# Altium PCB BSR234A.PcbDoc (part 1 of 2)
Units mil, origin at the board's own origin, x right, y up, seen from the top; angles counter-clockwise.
Board outline 3000 x 2500 mil, 4 copper layers (Top Layer, Signal Layer 1, Signal Layer 2, Bottom Layer), stack 61.2 mil thick; 82 components, 24 nets, 148 pads, 419 vias.
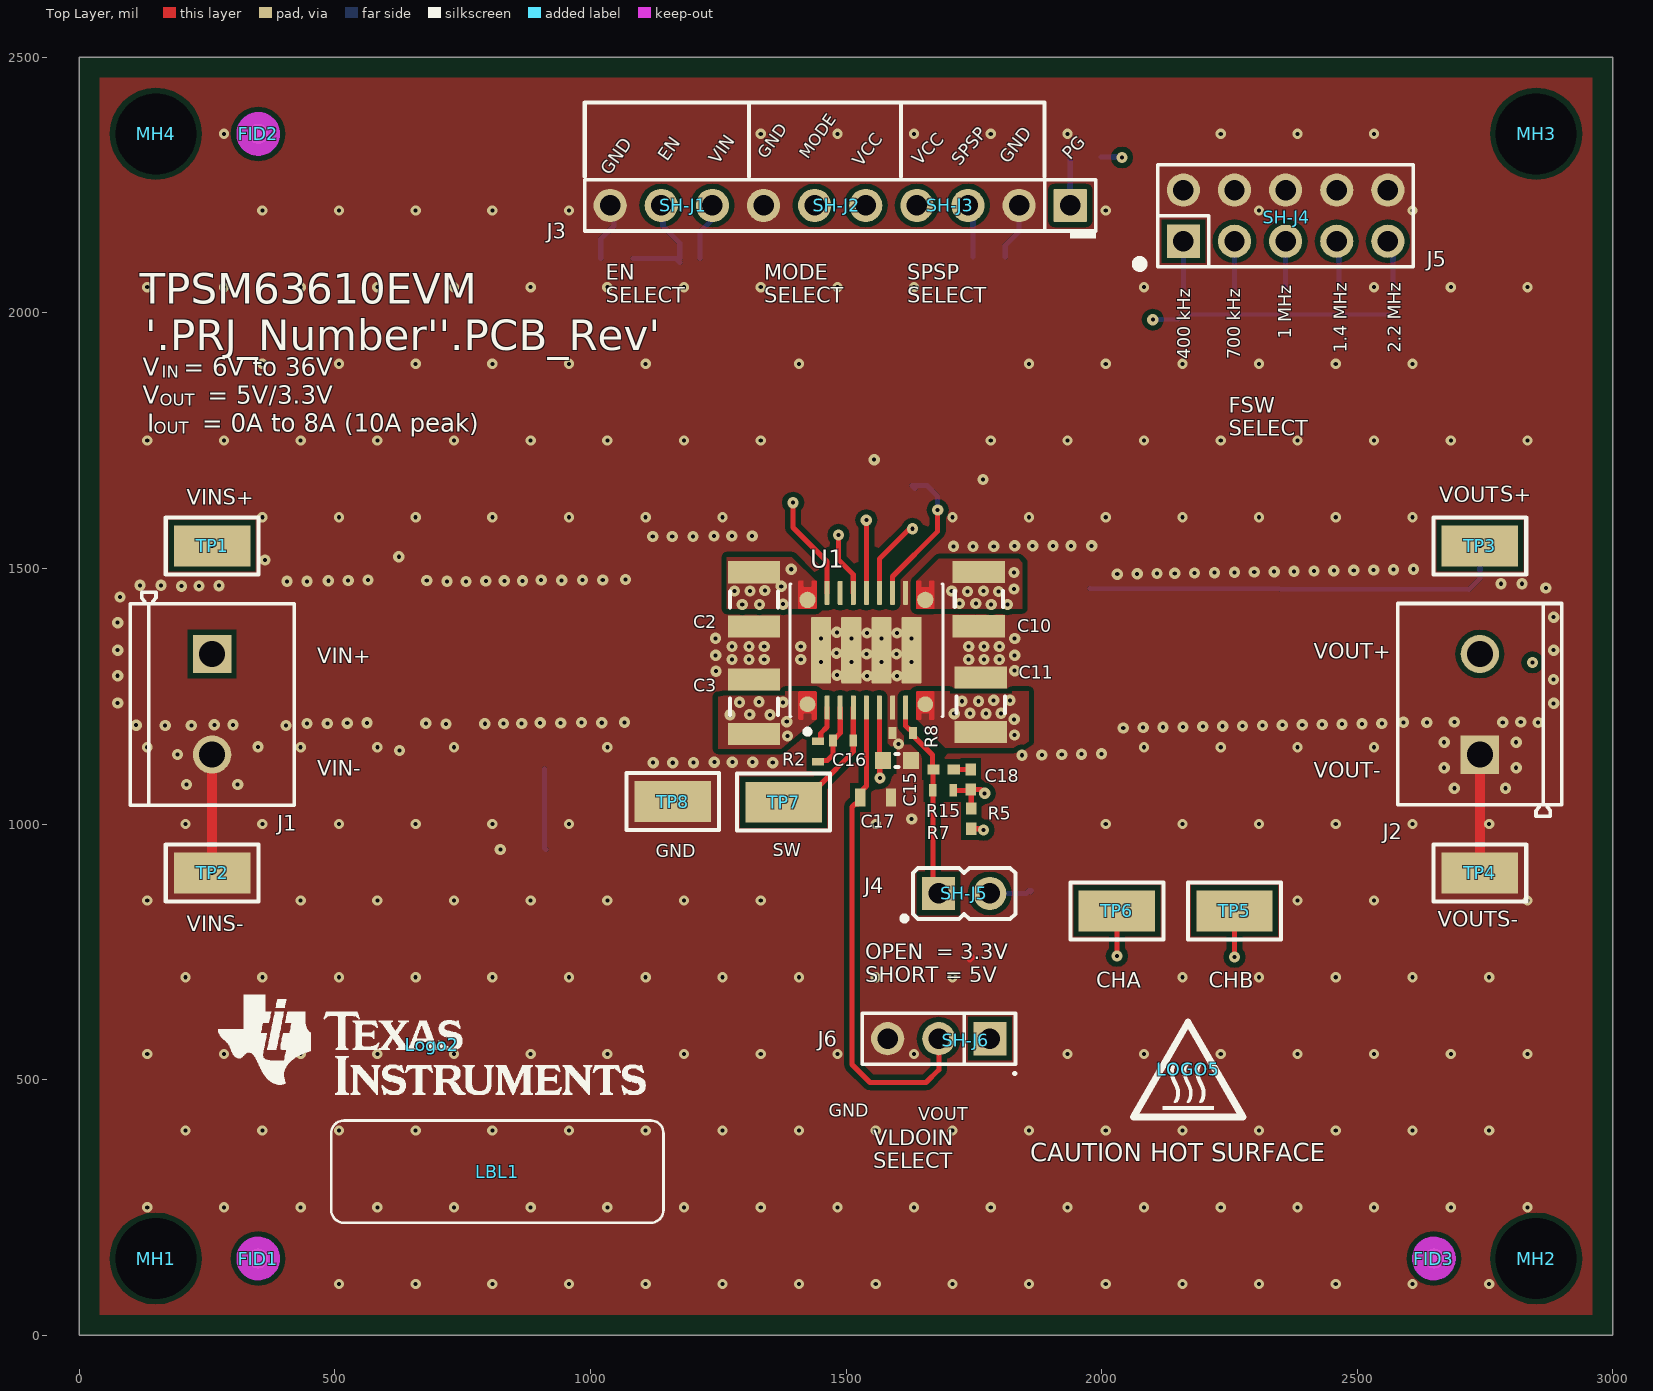
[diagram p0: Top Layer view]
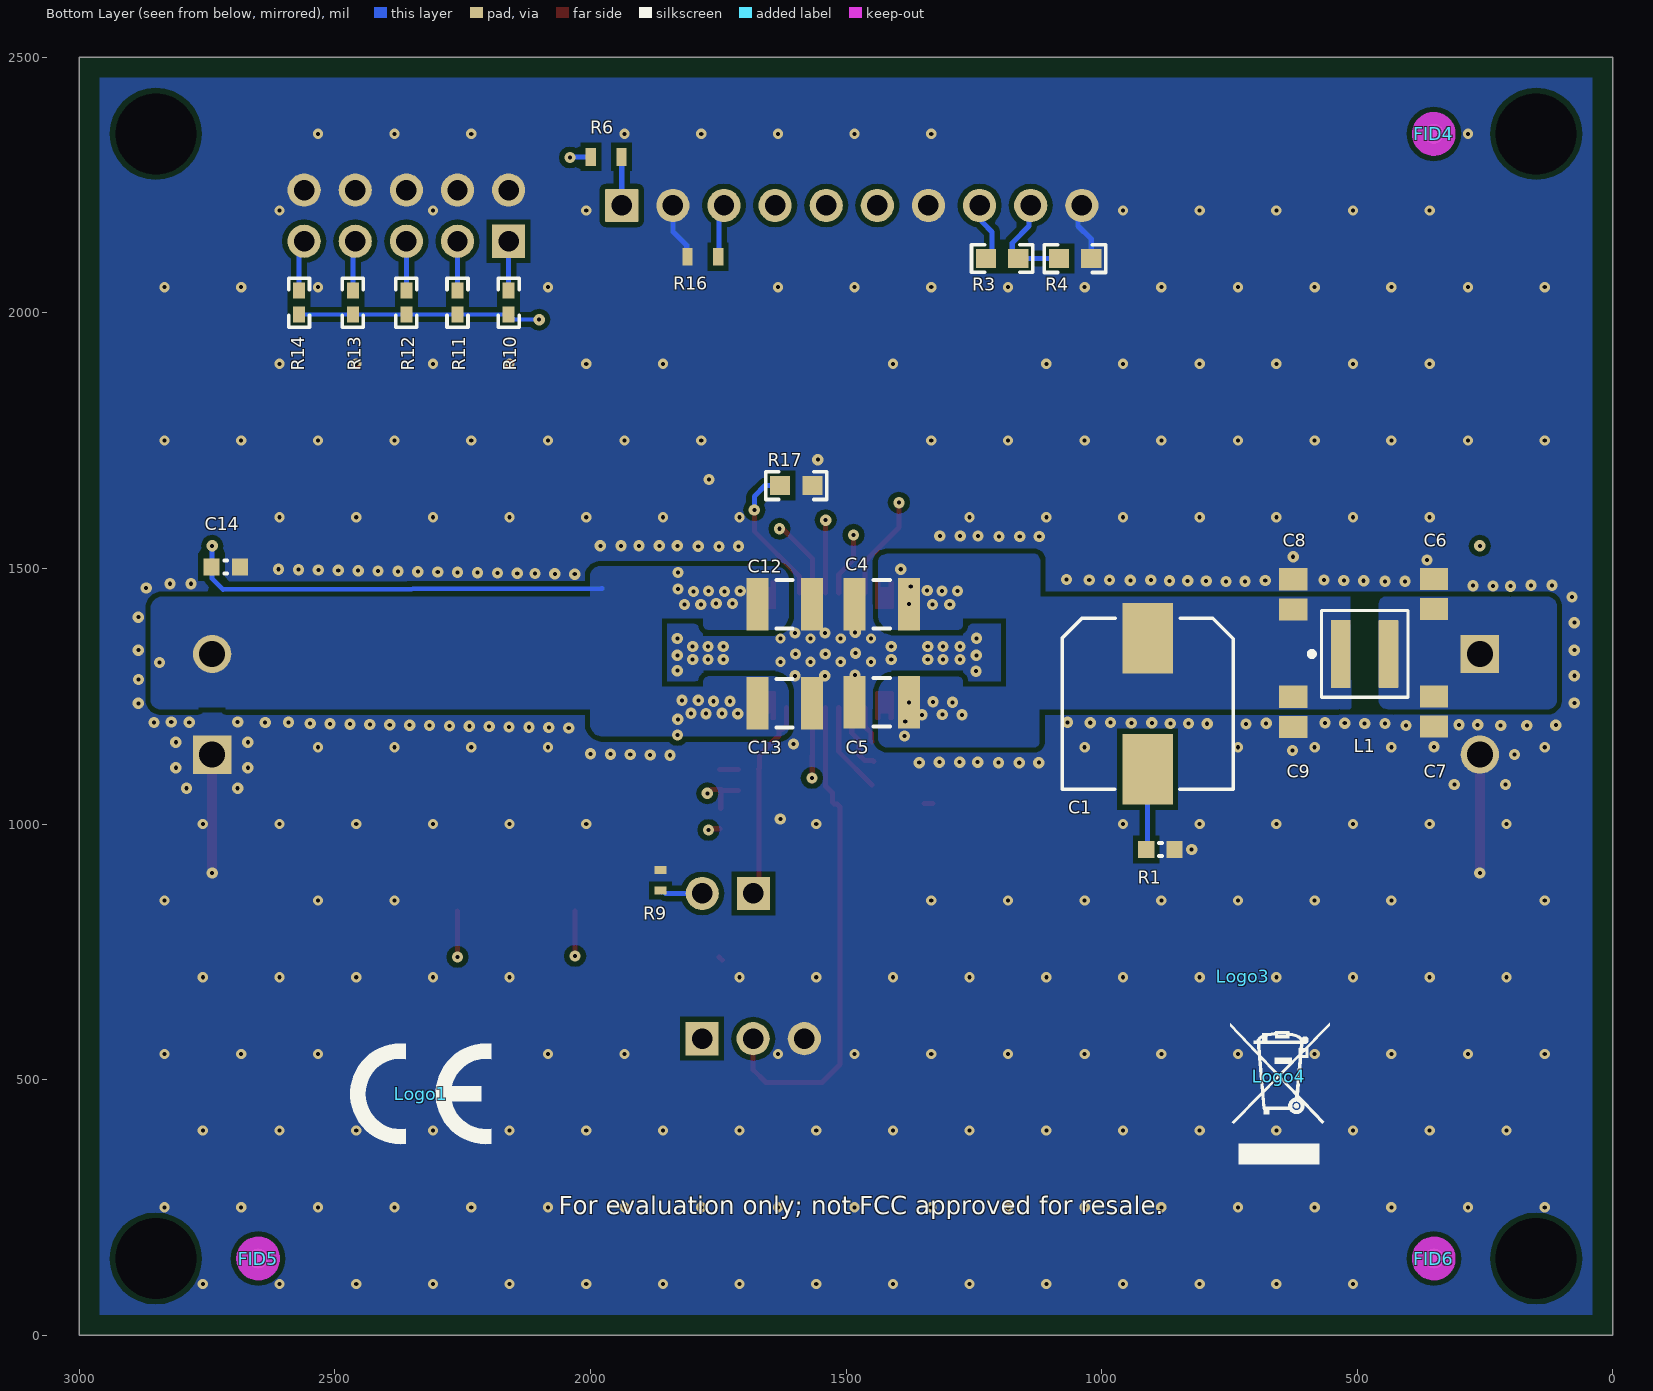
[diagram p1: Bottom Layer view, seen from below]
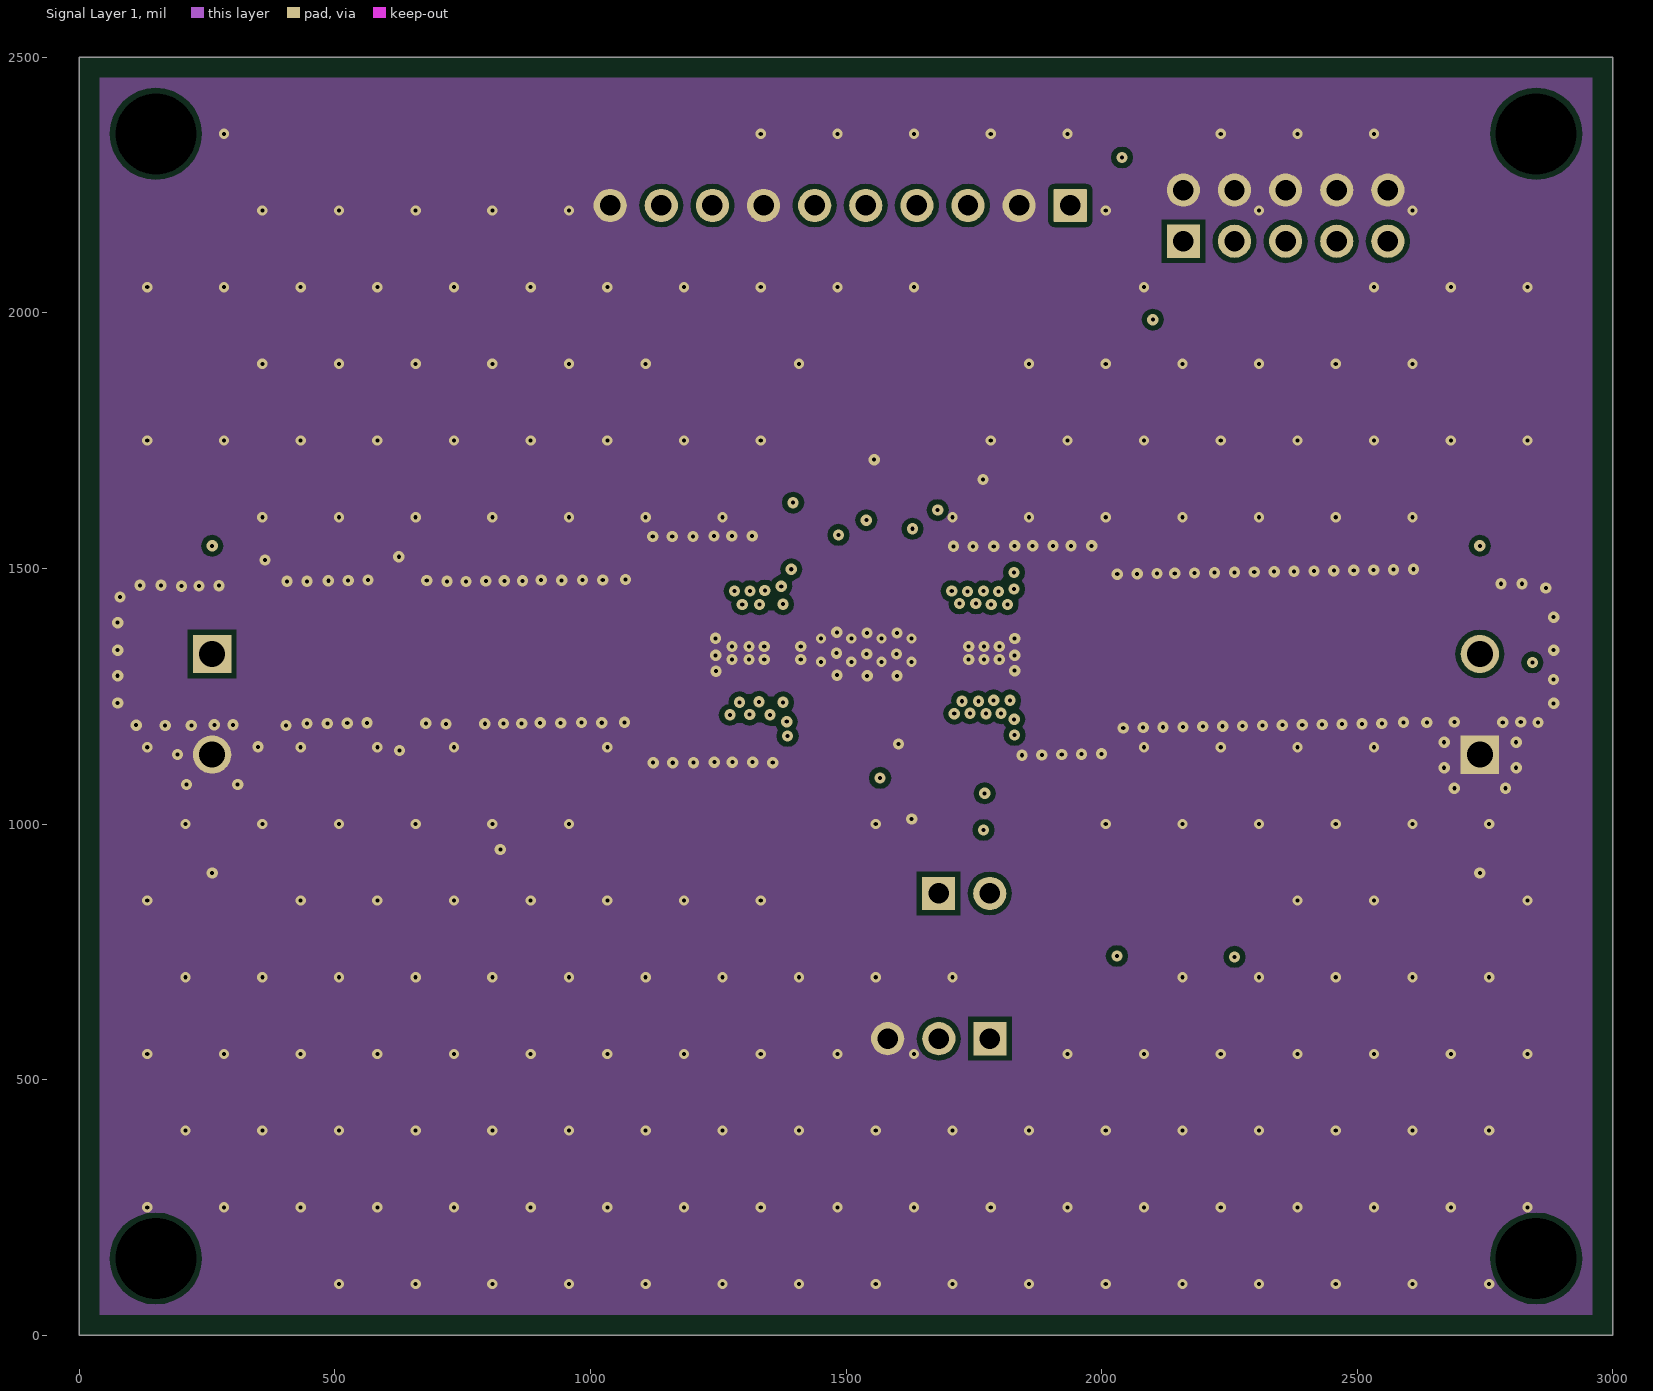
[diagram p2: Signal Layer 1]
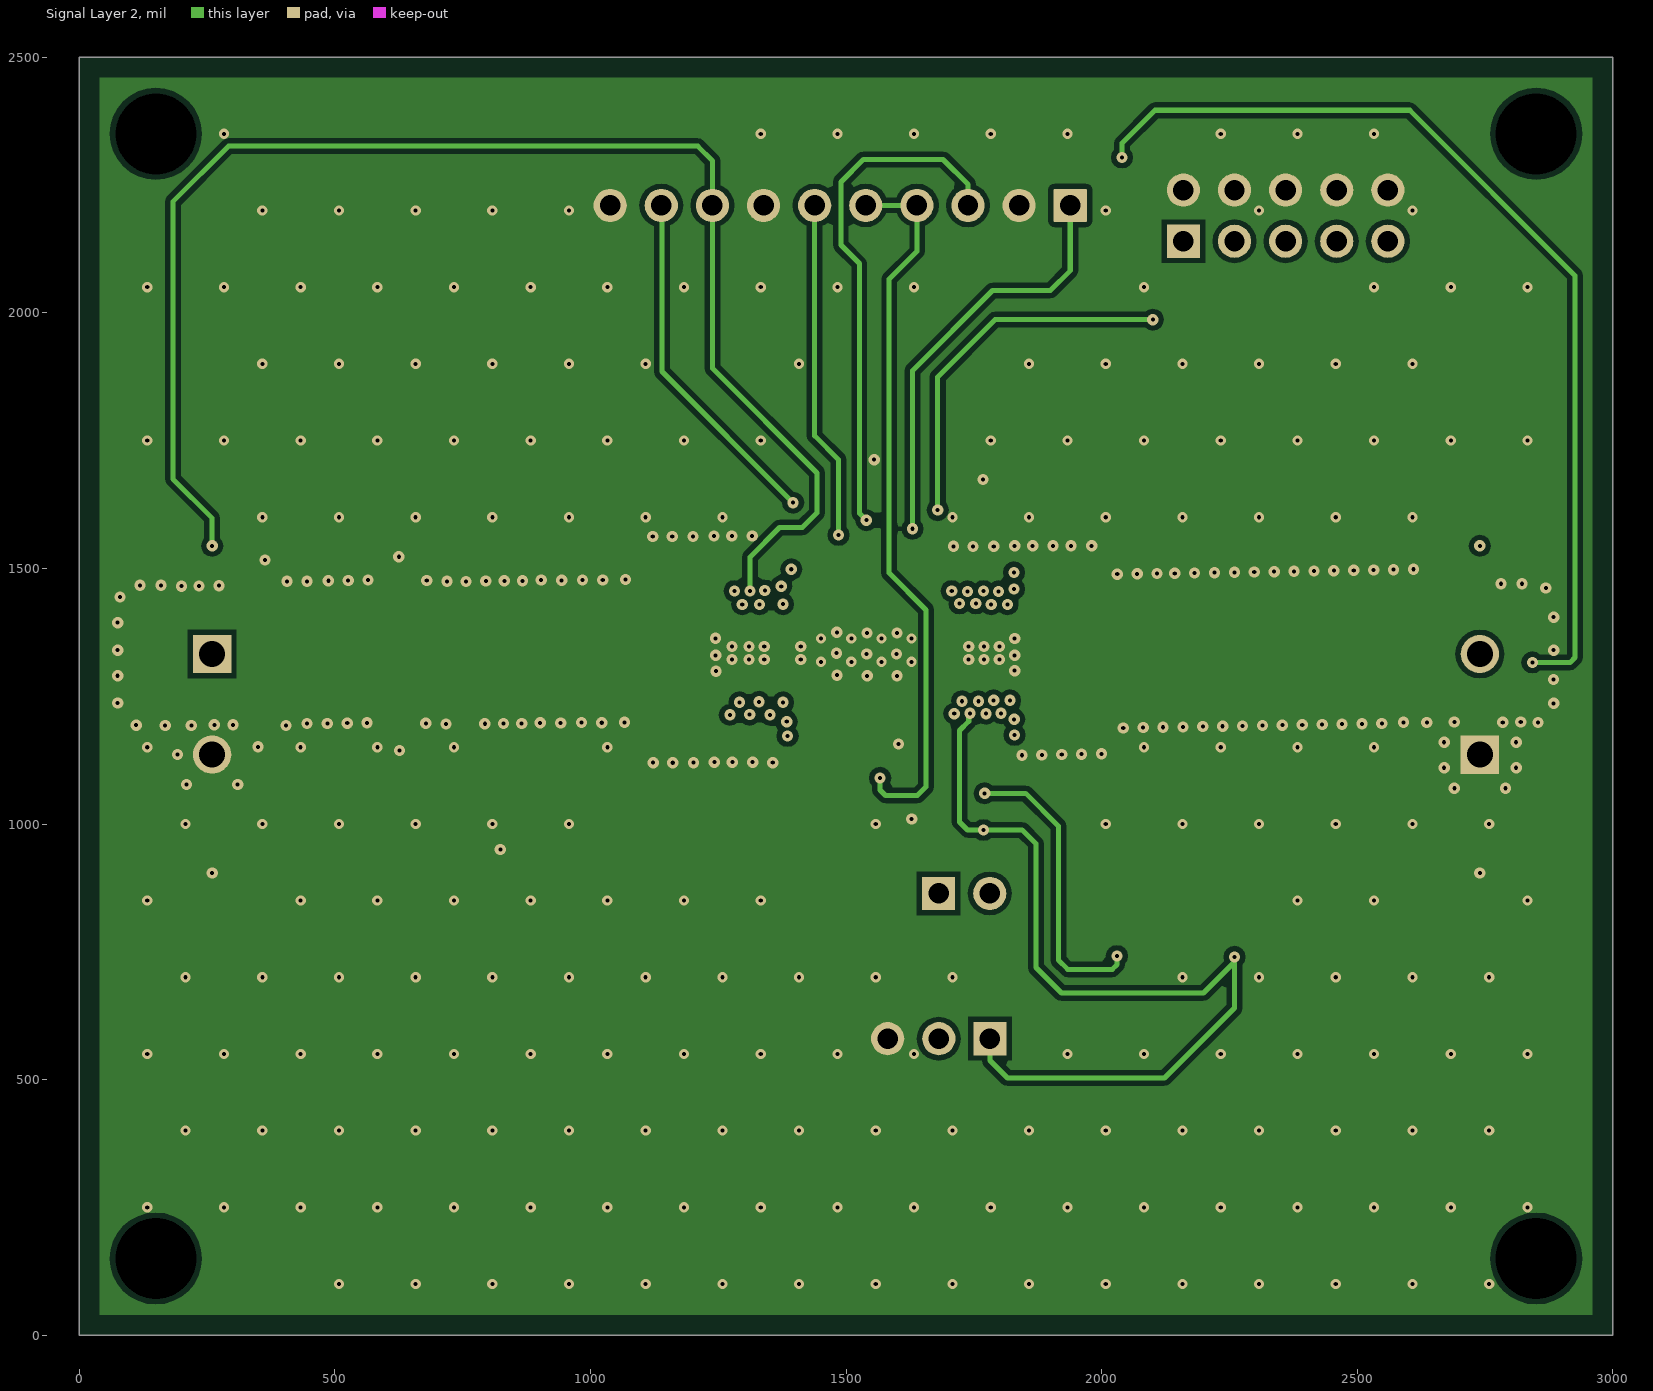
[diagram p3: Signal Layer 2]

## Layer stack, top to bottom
Top Solder: solder mask 0.4, Solder Resist, Dk 3.5
Top Layer: signal copper 2.8
Dielectric1: core 5, FR-4 High Tg, Dk 4.8
Signal Layer 1: signal copper 2.8
Dielectric3: dielectric 40, FR-4 High Tg, Dk 4.8
Signal Layer 2: signal copper 2.8
Dielectric2: dielectric 5, FR-4 High Tg, Dk 4.8
Bottom Layer: signal copper 2.8
Bottom Solder: solder mask 0.4, Solder Resist, Dk 3.5

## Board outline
0,0 3000,0 3000,2500 0,2500

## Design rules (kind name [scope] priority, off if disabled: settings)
AcuteAngle [All] p1: minimum=4.50000000000000E+0001 checktracksonly=FALSE
AssemblyTestPointUsage [All] p1: valid=2
BoardOutlineClearance BoardOutlineClearance_MountingHoles [OnCopper and InComponentClass('Mounting Holes')] p1: gap=39.37 ignorepadtopadclearanceinfootprint=FALSE
BoardOutlineClearance BoardOutlineClearance_Poly [OnCopper and IsPoly] p2: gap=40 ignorepadtopadclearanceinfootprint=FALSE
BoardOutlineClearance [OnCopper and Not InComponentClass('Logo') and not InComponentClass('FiducialMark') and not InRegion(1000,500,4000,800) and not InPoly] p3: gap=50 ignorepadtopadclearanceinfootprint=FALSE
Clearance Clearance_Keepouts [((IsTrack Or IsArc) And Not InPoly) And IsFree and IsKeepOut vs ((IsTrack Or IsArc) And Not InPoly) And IsFree and IsKeepOut] p1: gap=0 ignorepadtopadclearanceinfootprint=FALSE
Clearance Clearance_Poly [InPolygon] p2: gap=10 ignorepadtopadclearanceinfootprint=TRUE
Clearance Clearance_FiducialMark [IsKeepOut and InComponentClass('FiducialMark') vs IsPad and InComponentClass('FiducialMark')] p3: gap=0 ignorepadtopadclearanceinfootprint=FALSE
Clearance [All] p4: gap=7.87 ignorepadtopadclearanceinfootprint=TRUE
ComponentClearance ComponentClearance_MountingHoles_FiducialMarks [InComponentClass('Mounting Holes') vs InComponentClass('FiducialMark')] p1: gap=50 collisioncheckmode=3 verticalgap=10 showdistances=FALSE
ComponentClearance ComponentClearance_Shunt [InComponentClass('Header') vs InComponentClass('Shunt')] p2: gap=0 collisioncheckmode=3 verticalgap=0 showdistances=FALSE
ComponentClearance ComponentClearance_Logo [InComponentClass('Logo')] p3: gap=50 collisioncheckmode=3 verticalgap=10 showdistances=FALSE
ComponentClearance ComponentClearance_ScrewToNut [(HasFootprint('NY PMS 440 0025 PH')) vs (HasFootprint('Keystone_1902C'))] p4: gap=5 collisioncheckmode=3 verticalgap=10 showdistances=FALSE
ComponentClearance ComponentClearance_MountingHoles [InComponentClass('Mounting Holes')] p5: gap=250 collisioncheckmode=3 verticalgap=100000 showdistances=FALSE
ComponentClearance ComponentClearance_SmallPassives [HasFootprint('0201*') or HasFootprint('0402*') or HasFootprint('0508') or HasFootprint('0603*') or HasFootprint('0612') or HasFootprint('0805*') or HasFootprint('0815*') or HasFootprint('0830*') or HasFootprint('1206*') or HasFootprint('1210*') or HasFootprint('1808*') or HasFootprint('1812*') or HasFootprint('1825*') or HasFootprint('2010*') or HasFootprint('2220*') or HasFootprint('2225*') or HasFootprint('2512*') or HasFootprint('2728*') or HasFootprint('3518*') vs HasFootprint('0201*') or HasFootprint('0402*') or HasFootprint('0508') or HasFootprint('0603*') or HasFootprint('0612') or HasFootprint('0805*') or HasFootprint('0815*') or HasFootprint('0830*') or HasFootprint('1206*') or HasFootprint('1210*') or HasFootprint('1808*') or HasFootprint('1812*') or HasFootprint('1825*') or HasFootprint('2010*') or HasFootprint('2220*') or HasFootprint('2225*') or HasFootprint('2512*') or HasFootprint('2728*') or HasFootprint('3518*')] p6: gap=14.96 collisioncheckmode=3 verticalgap=10 showdistances=FALSE
ComponentClearance ComponentClearance_THtoSMT [IsThruComponent vs IsSMTComponent] p7: gap=40 collisioncheckmode=3 verticalgap=30 showdistances=FALSE
ComponentClearance ComponentClearance_THtoTH [IsThruComponent vs IsThruComponent] p8: gap=30 collisioncheckmode=3 verticalgap=30 showdistances=FALSE
ComponentClearance ComponentClearance_NetTie [HasFootprint('Net-Tie_10milWide_30milLong')] p9: gap=0 collisioncheckmode=3 verticalgap=0 showdistances=FALSE
ComponentClearance [All] p10: gap=15 collisioncheckmode=3 verticalgap=10 showdistances=FALSE
DiffPairsRouting [All] p1: maxlimit=100 minlimit=10 mostfreqgap=10 toplayer_minwidth=15 toplayer_maxwidth=15 toplayer_prefwidth=15 midlayer1_minwidth=15 midlayer1_maxwidth=15 midlayer1_prefwidth=15 midlayer2_minwidth=15 midlayer2_maxwidth=15 midlayer2_prefwidth=15 bottomlayer_minwidth=15 bottomlayer_maxwidth=15 bottomlayer_prefwidth=15 maxuncoupledlength=1000
FabricationTestPointUsage TestPointUsage [All] p1: valid=2 allowmultiple=FALSE
FabricationTestpoint Testpoint [All] p1: side=3 testpointundercomponent=TRUE minsize=40 maxsize=100 preferedsize=60 minholesize=0 maxholesize=40 preferedholesize=32 testpointgrid=1 allowsidetop=TRUE allowsidebottom=TRUE usegrid=TRUE gridtolerance=0.01
FanoutControl Fanout_LCC [IsLCC] p1: bgadir=Out bgaviamode=Centered fanoutstyle=Auto fanoutdirection=Alternating viagrid=1 // Fanout_LCC (Default Rule)
FanoutControl Fanout_BGA [IsBGA] p2: bgadir=Out bgaviamode=Centered fanoutstyle=Auto fanoutdirection=Alternating viagrid=1 // Fanout_BGA (Default Rule)
FanoutControl Fanout_Default [All] p4: bgadir=Out bgaviamode=Centered fanoutstyle=Auto fanoutdirection=Alternating viagrid=1 // Fanout_Default (Default Rule)
FanoutControl Fanout_Small [(CompPinCount < 5)] p5: bgadir=Out bgaviamode=Centered fanoutstyle=Auto fanoutdirection=OutThenIn viagrid=1 // Fanout_Small (Default Rule)
HoleSize [All] p1: absolutevalues=TRUE maxlimit=251 minlimit=7.87 maxpercent=80.000 minpercent=20.000
MinimumAnnularRing MinimumAnnularRing_ThermalPadVias [IsVia and InAnyComponent] p1: minimumring=5.91
MinimumAnnularRing [All] p2: minimumring=5.9
MinimumSolderMaskSliver MinimumSolderMaskSliver_Logo [InComponentClass('Logo') vs InComponentClass('Logo')] p1: minsoldermaskwidth=0.7
MinimumSolderMaskSliver [All] p2: minsoldermaskwidth=3.94
PlaneConnect [All] p1: planeconnectstyle=Relief reliefexpansion=10 reliefentries=4 reliefconductorwidth=10 reliefairgap=10
PolygonConnect PolygonConnect_TH [IsThruPin] p1: connectstyle=Direct reliefconductorwidth=10 reliefentries=4 polygonreliefangle="90 Angle" airgapwidth=10
PolygonConnect [All] p2: connectstyle=Direct reliefconductorwidth=10 reliefentries=4 polygonreliefangle="90 Angle" airgapwidth=10
RoutingVias ThermalPadVias [IsVia and InAnyComponent] p1: holewidth=7.87 width=19.68 viastyle="Through Hole" minholewidth=7.87 minwidth=19.68 maxholewidth=12.99 maxwidth=23.62
RoutingVias [All] p2: holewidth=10 width=22 viastyle="Through Hole" minholewidth=7.87 minwidth=8 maxholewidth=40 maxwidth=65
SilkToBoardRegionClearance [Not ((IsComment or IsDesignator) And (Hide <> 'False')) and not InRegion(1000,500,4000,800)] p1:
SilkToSilkClearance SilkToSilkClearance_Pb-FreeLogo [(HasFootprint('Pb-Free_Overlay_Medium') OR HasFootprint('Pb-Free_Overlay_Small')) vs (HasFootprint('Pb-Free_Overlay_Medium') OR HasFootprint('Pb-Free_Overlay_Small'))] p1: silktosilkclearance=0
SilkToSilkClearance [All] p2: silktosilkclearance=3.94
SilkToSolderMaskClearance SilkToComponentPadClearance [(IsPad or IsFill or IsRegion) and InAnycomponent] p1: minsilkscreentomaskgap=5 clearancetoexposedcopper=TRUE
SilkToSolderMaskClearance "Silk to Solder Mask Opening" [All] p2: minsilkscreentomaskgap=3.94 clearancetoexposedcopper=FALSE
SolderMaskExpansion [All] p1: expansion=1.97 istentingtop=FALSE
UnRoutedNet [All] p1: checkbadconnections=TRUE
Width [All] p1: maxlimit=100 minlimit=6 preferedwidth=10 checkconnectedcopper=TRUE
14 further rules are at their usual default settings.

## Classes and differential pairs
component class AssemblyNote: ZZ1 ZZ2 ZZ3 ZZ4 ZZ5 ZZ6 ZZ7 ZZ8 ZZ9
component class FiducialMark: FID1 FID2 FID3 FID4 FID5 FID6
component class Logo: Logo2
component class BSR234A_Hardware: !PCB1 FID1 FID2 FID3 FID4 FID5 FID6 H1 H2 H3 H4 H5 H6 H7 H8 LBL1 Logo1 Logo2 Logo3 Logo4 LOGO5 MH1 MH2 MH3 MH4 SH-J1 SH-J2 SH-J3 SH-J4 SH-J5 SH-J6 ZZ1 ZZ2 ZZ3 ZZ4 ZZ5 ZZ6 ZZ7 ZZ8 ZZ9
component class BSR234A: C1 C2 C3 C4 C5 C6 C7 C8 C9 C10 C11 C12 C13 C14 C15 C16 C17 C18 J1 J2 J3 J4 J5 J6 L1 R1 R2 R3 R4 R5 R6 R7 R8 R9 R10 R11 R12 R13 R14 R15 R16 R17 TP1 TP2 TP3 TP4 TP5 TP6 TP7 TP8 U1
component class Header: J3 J4 J5 J6
component class Shunt: SH-J1 SH-J2 SH-J3 SH-J4 SH-J5 SH-J6
component class Label: LBL1

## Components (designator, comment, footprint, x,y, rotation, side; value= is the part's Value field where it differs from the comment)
C1 "UUD1H101MNL1GS" SM_RADIAL_8MM 910,1235 r270 bottom value=100uF
C2 "GRM32ER71H106KA12L" 1210_270L 1320.16,1439.32 r90 top value=10uF
C3 "GRM32ER71H106KA12L" 1210_270L 1320.16,1229.32 r270 top value=10uF
C4 "GRM32ER71H106KA12L" 1210_270L 1430,1430 r180 bottom value=10uF
C5 "GRM32ER71H106KA12L" 1210_270L 1430,1238 r180 bottom value=10uF
C6 "CGA4J3X7R1H225K125AB" 0805L 350,1450 r90 bottom value=2.2uF
C7 "CGA4J3X7R1H225K125AB" 0805L 350,1220 r270 bottom value=2.2uF
C8 "CGA4J3X7R1H225K125AB" 0805L 625.16,1449.32 r90 bottom value=2.2uF
C9 "CGA4J3X7R1H225K125AB" 0805L 625.16,1219.32 r270 bottom value=2.2uF
C10 "GRM32EC81C476ME15L" 1210_270L 1760,1440 r90 top value=47uF
C11 "GRM32EC81C476ME15L" 1210_270L 1763.8,1233.35 r270 top value=47uF
C12 "GRM32EC81C476ME15L" 1210_270L 1620,1430 r180 bottom value=47uF
C13 "GRM32EC81C476ME15L" 1210_270L 1620,1236.11 r180 bottom value=47uF
C14 "CGA3E2X7R1E104K080AA" 0603L 2713.43,1502.69 r180 bottom value=0.1uF
C15 "Capacitor" 0603L 1599.89,1124.58 r0 top value=1uF
C16 "CBOOT" 0402S 1494.41,1163.53 r180 top value=0.1uF
C17 "CBIAS" 0603S 1557.93,1051.76 r180 top value=0.15uF
C18 "CGA2B2C0G1H100D050BA" 0402L 1744.06,1087.07 r90 top value=10pF
FID1 "Fiducial" Fiducial10-20 350,150 r0 top
FID2 "Fiducial" Fiducial10-20 350,2350 r0 top
FID3 "Fiducial" Fiducial10-20 2650,150 r0 top
FID4 "Fiducial" Fiducial10-20 350,2350 r180 bottom
FID5 "Fiducial" Fiducial10-20 2650,150 r180 bottom
FID6 "Fiducial" Fiducial10-20 350,150 r180 bottom
J1 "1729018" Phoenix_1729018 260,1234.16 r270 top
J2 "1729018" Phoenix_1729018 2740,1234.16 r90 top
J3 "TSW-110-07-G-S" TSW-110-07-G-S 1488.67,2210 r180 top
J4 "PBC02SAAN" Sullins_PBC02SAAN 1731.23,864.16 r90 top
J5 "PEC05DAAN" CONN_PEC05DAAN 2360,2190 r0 top
J6 "PBC03SAAN" PBC03SAAN 1681.57,580 r180 top
L1 "XGL4030-152MEC" FP-XGL4030-152MEC_SMT2_4MM0_4MM0-MFG 485.35,1332.58 r180 bottom value=1.5uH
LBL1 "THT-14-423-10" Label_650x200 817.95,320 r180 top
Logo1 "CE Mark" CE_Mark_5mm 2332,472 r180 bottom
Logo2 "Texas Instruments" TI_Stacked_Overlay_Small 690,568.18 r0 top
Logo3 "FCC disclaimer" FCC_disclaimer 724.17,701.97 r180 bottom
Logo4 "WEEE logo" WEEE_Minimum 653,507 r180 bottom
LOGO5 "CAUTION HOT SURFACE" IEC_HotSurface_Small 2169.25,520 r0 top
MH1 "MTG_NoPads" MTG_159mil 150,150 r0 top
MH2 "MTG_NoPads" MTG_159mil 2850,150 r0 top
MH3 "MTG_NoPads" MTG_159mil 2850,2350 r0 top
MH4 "MTG_NoPads" MTG_159mil 150,2350 r0 top
R1 "CRCW06030000Z0EA" 0603L 885,950 r0 bottom value=0
R2 "CRCW04020000Z0EDHP" 0402S 1445.09,1142.06 r270 top value=0
R3 "CRCW0603187KFKEA" 0603 1194.45,2106.16 r180 bottom value=187k
R4 "CRCW060349K9FKEA" 0603 1051.83,2106.16 r0 bottom value=49.9k
R5 "CRCW040210R0FKED" 0402L 1745.01,1010.46 r270 top value=10.0
R6 "RRESET" 0603S 1969.2,2304.98 r0 bottom value=100k
R7 "RFBT" 0402S 1690,1065.91 r0 top value=100k
R8 "RFBB" 0402S 1611.03,1177.8 r0 top value=43.2k
R9 "RFBB5V" 0402S 1863.08,890 r270 bottom value=59.0k
R10 "CRCW040240K2FKED" 0402 2160,2020 r270 bottom value=40.2k
R11 "CRCW040222K6FKED" 0402 2260,2020 r270 bottom value=22.6k
R12 "CRCW040215K8FKED" 0402 2360,2020 r270 bottom value=15.8k
R13 "CRCW040211K0FKED" 0402 2464.6,2020 r270 bottom value=11.0k
R14 "CRCW04026K80JNED" 0402 2570,2020 r270 bottom value=6.8k
R15 "CRCW04024K99FKED" 0402L 1691.07,1106.38 r0 top value=4.99k
R16 "CRCW060316K5FKEA" 0603S 1780,2109.7 r180 bottom value=16.5k
R17 "CRCW06034M99FKEA" 0603 1597.25,1662 r0 bottom value=4.99Meg
SH-J1 "SNT-100-BK-G" SNT-100-BK-G 1181.52,2210 r180 top value=1x2
SH-J2 "SNT-100-BK-G" SNT-100-BK-G 1481.52,2210 r180 top value=1x2
SH-J3 "SNT-100-BK-G" SNT-100-BK-G 1704.05,2210 r0 top value=1x2
SH-J4 "SNT-100-BK-G" SNT-100-BK-G 2362,2187 r270 top value=1x2
SH-J5 "SNT-100-BK-G" SNT-100-BK-G 1731.23,864.16 r0 top value=1x2
SH-J6 "SNT-100-BK-G" SNT-100-BK-G 1734.74,577.22 r180 top value=1x2
TP1 "VIN+" Keystone_5019 260,1544.16 r0 top
TP2 "VIN-" Keystone_5019 260,904.16 r180 top
TP3 "5019" Keystone_5019 2740,1544.16 r180 top
TP4 "5019" Keystone_5019 2740,904.16 r180 top
TP5 "CHB" Keystone_5019 2260,830 r180 top
TP6 "CHA" Keystone_5019 2030,830 r0 top
TP7 "SW" Keystone_5019 1377.82,1042.64 r0 top
TP8 "GND" Keystone_5019 1161.01,1043.91 r0 top
U1 "TPSM63610RDFR" RDF0022A-MFG 1539.85,1340 r90 top
ZZ1 "This Assembly Note is for PCB labels only" AssemblyNoteLabel 160,3920 r0 top
ZZ2 "These assemblies must be clean and free from flux and all contaminants. Use of no clean flux is not acceptable." AssemblyNote 158.91,3819.12 r0 top
ZZ3 "These assemblies must comply with workmanship standards IPC-A-610 Class 2, unless otherwise specified." AssemblyNote 158.91,3726.6 r0 top
ZZ4 "Place SH-J1 on J3 pins 8 and 9" AssemblyNote 158.91,3634.08 r0 top
ZZ5 "Place SH-J2 on J3 pins 5 and 6" AssemblyNote 158.91,3541.56 r0 top
ZZ6 "Place SH-J3 on J3 pins 3 and 4" AssemblyNote 158.91,3449.04 r0 top
ZZ7 "Place SH-J4 on J5 pins 5 and 6" AssemblyNote 160,3350 r0 top
ZZ8 "Place SH-J5 on J4 pins 2 and 3" AssemblyNote 160,3240 r0 top
ZZ9 "Place SH-J6 on J6 pins 1 and 2" AssemblyNote 160,3120 r0 top

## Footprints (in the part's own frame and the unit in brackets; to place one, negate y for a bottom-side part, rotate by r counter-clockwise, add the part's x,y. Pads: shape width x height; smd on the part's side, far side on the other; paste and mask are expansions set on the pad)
0402 [mm] "0402 from SM-752 data"
  rect 0.8x0.6 smd: 1(-0.6,0) 2(0.6,0)
  silkscreen extent -1.22,-0.52 1.22,0.52, body extent -0.55,-0.3 0.55,0.3, height 0.6
0402L [mm] "0402 from SM-752 data"
  rect 0.6x0.5 smd: 1(-0.5,0) 2(0.5,0)
  body extent -0.55,-0.3 0.55,0.3, height 0.6
0402S [mil] "Based on C0402S footprint from PADS legacy"
  rect 15x24 smd: 1(-20,0) 2(20,0)
  body extent -22,-12 22,12, height 24
0603 [mm] "0603 from SM-752 data"
  rect 1x0.95 smd: 1(-0.8,0) 2(0.8,0)
  silkscreen extent -1.52,-0.69 1.52,0.69, body extent -0.87,-0.47 0.87,0.47, height 1
0603L [mm] "0603 from SM-752 data"
  rect 0.8x0.85 smd: 1(-0.7,0) 2(0.7,0)
  silkscreen extent -0.07,-0.33 0.07,0.33, body extent -0.87,-0.47 0.87,0.47, height 1
0603S [mil]
  rect 20x35 smd: 1(-30,0) 2(30,0)
  body extent -34,-19 34,19, height 39
0805L [mm] "0805 from SM-752 data"
  rect 1.1x1.4 smd: 1(-0.75,0) 2(0.75,0)
  body extent -1.1,-0.72 1.1,0.72, height 1.45
1210_270L [mm] "1210"
  rect 1.1x2.6 smd: 1(-1.35,0) 2(1.35,0)
  silkscreen extent -0.4,-1.2 0.4,1.2, body extent -1.7,-1.35 1.7,1.35, height 2.7
AssemblyNote [mil] "Assembly Note"
AssemblyNoteLabel [mil] "Assembly Note for PCB Labels"
CE_Mark_5mm [mil] "Minimum text height for CE Mark"
  silkscreen extent -138,-98 138,98
CONN_PEC05DAAN [mm] "SULLINS"
  rect 1.65x1.65 hole 1.016 mask+0: 1(-5.08,-1.27)
  round 1.65 hole 1.016 mask+0: 2(-5.08,1.27) 3(-2.54,-1.27) 4(-2.54,1.27) 5(0,-1.27) 6(0,1.27) 7(2.54,-1.27) 8(2.54,1.27) 9(5.08,-1.27) 10(5.08,1.27)
  silkscreen extent -7.45,-2.6 6.35,2.54, body extent -6.35,-2.54 6.35,2.54, height 8.38
FCC_disclaimer [mil]
Fiducial10-20 [mm]
  round 1 smd mask+0.5: 1(0,0)
  Top Layer keep-out circle w1.178: c0,0 r0.5
FP-XGL4030-152MEC_SMT2_4MM0_4MM0-MFG [mm]
  rrect10% 0.98x3.4 smd paste+0 mask+0: 1(-1.185,0) 2(1.185,0)
  silkscreen extent -2.75,-2.15 2.15,2.15, body extent -2,-2 2,2, height 3.1
IEC_HotSurface_Small [mil]
  silkscreen extent -107,-93 107,92
Keystone_5019 [mm] "Test Point, Miniature, SMT"
  rect 3.8x2.03 smd: 1(0,0)
  silkscreen extent -2.31,-1.42 2.31,1.42, body extent -1.9,-1.02 1.9,1.02, height 2.29
Label_650x200 [mil] "Thermal Transfer Label"
  round 1 on Mech13: 0(0,0)
  silkscreen extent -325,-100 325,100, body extent -325,-100 325,100, height 1
MTG_159mil [mil] "159mil Non Plated Hole"
  round 150 hole 159 unplated: 1(0,0)
PBC03SAAN [mm] "Sullins 100mil, 1x3, 230 mil above insulator"
  rect 1.65x1.65 hole 1.016: 1(-2.54,0)
  round 1.65 hole 1.016: 2(0,0) 3(2.54,0)
  silkscreen extent -3.81,-1.27 3.81,1.27, body extent -3.81,-1.27 3.81,1.27, height 8.38
Phoenix_1729018 [mm] "Phoenix Contact"
  rect 1.905x1.905 hole 1.3: 1(-2.5,0)
  round 1.9 hole 1.3: 2(2.5,0)
  silkscreen extent -5.56,-4.08 5.01,4.07, body extent -5.56,-4.08 5.01,4.07, height 10
RDF0022A-MFG [mm]
  round 0.787 smd paste+0 mask-1000: 1(-2.688,2.925) 9(-2.688,-2.925)
  rrect40% 1.2x0.25 smd paste+0 mask-1000: 2(-2.85,1.95) 3(-2.85,1.3) 4(-2.85,0.65) 5(-2.85,0) 6(-2.85,-0.65) 7(-2.85,-1.3) 8(-2.85,-1.95) 11(2.85,-1.95) 12(2.85,-1.3) 13(2.85,-0.65) 14(2.85,0) 15(2.85,0.65) 16(2.85,1.3) 17(2.85,1.95)
  round 0.81 smd paste+0 mask-1000: 10(2.5,-2.925) 18(2.5,2.925)
  rrect10% 3.3x1 smd paste-1000 mask-1000: 19(0,2.25) 20(0,0.75) 21(0,-0.75) 22(0,-2.25)
  Top Layer region: -3.45,3.325 -3.443,3.35 -3.425,3.368 -3.4,3.375 -3.4,3.375 -2.1,3.375 -2.075,3.368 -2.057,3.35 -2.05,3.325 -2.05,3.325 -2.05,2.525 -2.054,2.506 -2.065,2.49 -2.081,2.479 -2.1,2.475 -2.1,2.475 -3.4,2.475 -3.419,2.479 -3.435,2.49 -3.446,2.506 -3.45,2.525 -3.45,2.525 -3.45,2.675 -3.443,2.7 -3.425,2.718 -3.4,2.725 -3.4,2.725 -3.175,2.725 -3.156,2.729 -3.14,2.74 -3.129,2.756 -3.125,2.775 -3.125,2.775 -3.125,3.075 -3.129,3.094 -3.14,3.11 -3.156,3.121 -3.175,3.125 -3.175,3.125 -3.4,3.125 -3.419,3.129 -3.435,3.14 -3.446,3.156 -3.45,3.175 -3.45,3.175
  Top Layer region: -3.45,-3.325 -3.443,-3.35 -3.425,-3.368 -3.4,-3.375 -3.4,-3.375 -2.1,-3.375 -2.075,-3.368 -2.057,-3.35 -2.05,-3.325 -2.05,-3.325 -2.05,-2.525 -2.054,-2.506 -2.065,-2.49 -2.081,-2.479 -2.1,-2.475 -2.1,-2.475 -3.4,-2.475 -3.419,-2.479 -3.435,-2.49 -3.446,-2.506 -3.45,-2.525 -3.45,-2.525 -3.45,-2.675 -3.443,-2.7 -3.425,-2.718 -3.4,-2.725 -3.4,-2.725 -3.175,-2.725 -3.156,-2.729 -3.14,-2.74 -3.129,-2.756 -3.125,-2.775 -3.125,-2.775 -3.125,-3.075 -3.129,-3.094 -3.14,-3.11 -3.156,-3.121 -3.175,-3.125 -3.175,-3.125 -3.4,-3.125 -3.419,-3.129 -3.435,-3.14 -3.446,-3.156 -3.45,-3.175 -3.45,-3.175
  Top Layer region: 3.45,-3.325 3.443,-3.35 3.425,-3.368 3.4,-3.375 3.4,-3.375 2.1,-3.375 2.075,-3.368 2.057,-3.35 2.05,-3.325 2.05,-3.325 2.05,-2.525 2.054,-2.506 2.065,-2.49 2.081,-2.479 2.1,-2.475 2.1,-2.475 3.4,-2.475 3.419,-2.479 3.435,-2.49 3.446,-2.506 3.45,-2.525 3.45,-2.525 3.45,-2.675 3.443,-2.7 3.425,-2.718 3.4,-2.725 3.4,-2.725 3.175,-2.725 3.156,-2.729 3.14,-2.74 3.129,-2.756 3.125,-2.775 3.125,-2.775 3.125,-3.075 3.129,-3.094 3.14,-3.11 3.156,-3.121 3.175,-3.125 3.175,-3.125 3.4,-3.125 3.419,-3.129 3.435,-3.14 3.446,-3.156 3.45,-3.175 3.45,-3.175
  Top Layer region: 3.45,3.325 3.443,3.35 3.425,3.368 3.4,3.375 3.4,3.375 2.1,3.375 2.075,3.368 2.057,3.35 2.05,3.325 2.05,3.325 2.05,2.525 2.054,2.506 2.065,2.49 2.081,2.479 2.1,2.475 2.1,2.475 3.4,2.475 3.419,2.479 3.435,2.49 3.446,2.506 3.45,2.525 3.45,2.525 3.45,2.675 3.443,2.7 3.425,2.718 3.4,2.725 3.4,2.725 3.175,2.725 3.156,2.729 3.14,2.74 3.129,2.756 3.125,2.775 3.125,2.775 3.125,3.075 3.129,3.094 3.14,3.11 3.156,3.121 3.175,3.125 3.175,3.125 3.4,3.125 3.419,3.129 3.435,3.14 3.446,3.156 3.45,3.175 3.45,3.175
  silkscreen extent -4.17,-3.8 3.3,3.8, body extent -3.55,-3.9 3.55,3.9, height 0.25
SM_RADIAL_8MM [mm] "Nichicon 8x10"
  rect 3.5x2.5 smd: 1(-3.25,0) 2(3.25,0)
  silkscreen extent -4.25,-4.25 4.25,4.25, body extent -4.25,-4.25 4.25,4.25, height 10.5
SNT-100-BK-G [mil] "Samtec STEP model"
  round 1 on Mech3: 0(0,0)
  body extent -100,-50 100,50, height 344
Sullins_PBC02SAAN [mm] "Sullins 100mil, 1x2, 230 mil above insulator"
  rect 1.65x1.65 hole 1.016: 1(0,1.27)
  round 1.65 hole 1.016: 2(0,-1.27)
  silkscreen extent -1.37,-2.54 1.27,3.1, body extent -1.27,-2.54 1.27,2.54, height 8.38
TI_Stacked_Overlay_Small [mil]
  silkscreen extent -418,-98 418,98
TSW-110-07-G-S [mm] "Samtec 100mil, 1x10, 230 mil above insulator"
  rrect6% 1.65x1.65 hole 1.016: 1(-11.43,0)
  round 1.65 hole 1.016: 2(-8.89,0) 3(-6.35,0) 4(-3.81,0) 5(-1.27,0) 6(1.27,0) 7(3.81,0) 8(6.35,0) 9(8.89,0) 10(11.43,0)
  silkscreen extent -12.7,-1.27 12.7,1.65, body extent -12.7,-1.27 12.7,1.27, height 8.38
WEEE_Minimum [mil] "WEEElie bin"
  silkscreen extent -95,-172 99,104

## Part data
C1: library part CMP-0011414-2, "CAP, AL, 100 uF, 50 V, +/- 20%, 0.34 ohm, SMD", Cap_Case=8x10, Manufacturer=Nichicon, Supplier Part Number 1=493-2306-1-ND, Tolerance_%=20%, Value1="0.34 ohm", Value2=50V, ValueDisplayed=100uF
C2 C3 C4 C5: library part CMP-0009226-3, "CAP, CERM, 10 uF, 50 V, +/- 10%, X7R, 1210", Cap_Case=1210, Manufacturer=MuRata, Supplier Part Number 1=490-6544-1-ND, TempCo=X7R, Tolerance_%=10%, Value1=Unknown, Value2=50V, ValueDisplayed=10uF
C6 C7 C8 C9: library part CMP-0007977-2, "CAP, CERM, 2.2 uF, 50 V, +/- 10%, X7R, AEC-Q200 Grade 1, 0805", Cap_Case=0805, Manufacturer=TDK, Supplier Part Number 1=445-174216-1-ND, TempCo=X7R, Tolerance_%=10%, Value1="0.003288 ohm", Value2=50V, ValueDisplayed=2.2uF
C10 C11 C12 C13: library part CMP-0009201-2, "CAP, CERM, 47 uF, 16 V, +/- 20%, X6S, 1210", Cap_Case=1210, Manufacturer=MuRata, Supplier Part Number 1=490-9968-1-ND, TempCo=X6S, Tolerance_%=20%, Value1=Unknown, Value2=16V, ValueDisplayed=47uF
C14: library part CMP-0007077-5, "CAP, CERM, 0.1 uF, 25 V, +/- 10%, X7R, AEC-Q200 Grade 1, 0603", Cap_Case=0603, Manufacturer=TDK, Supplier Part Number 1=445-5667-1-ND, TempCo=X7R, Tolerance_%=10%, Value1=Unknown, Value2=25V, ValueDisplayed=0.1uF
C15: library part CMP-0006867-4, "CAP, CERM, 1 uF, 25 V, +/- 10%, X7R, 0603", Cap_Case=0603, Manufacturer=Kemet, PartNumber=C0603C105K3RACTU, Supplier Part Number 1=399-7376-1-ND, TempCo=X7R, Tolerance_%=10%, Value1=Unknown, Value2=25V, ValueDisplayed=1uF
C16: library part CMP-0006325-2, "CAP, CERM, 0.1 uF, 50 V, +/- 10%, X7R, AEC-Q200 Grade 1, 0402", Cap_Case=0402, Manufacturer=TDK, PartNumber=CGA2B3X7R1H104K050BB, Supplier Part Number 1=445-6899-1-ND, TempCo=X7R, Tolerance_%=10%, Value1="0.039064 ohm", Value2=50V, ValueDisplayed=0.1uF
C17: library part CMP-0007093-5, "CAP, CERM, 0.15 uF, 50 V, +/- 10%, X7R, AEC-Q200 Grade 1, 0603", Cap_Case=0603, Manufacturer=TDK, PartNumber=CGA3E3X7R1H154K080AB, Supplier Part Number 1=445-6925-1-ND, TempCo=X7R, Tolerance_%=10%, Value1="0.028863 ohm", Value2=50V, ValueDisplayed=0.15uF
C18: library part CMP-0006307-2, "CAP, CERM, 10 pF, 50 V, +/- 5%, C0G/NP0, AEC-Q200 Grade 1, 0402", Cap_Case=0402, Manufacturer=TDK, Supplier Part Number 1=445-5584-1-ND, TempCo=C0G/NP0, Tolerance_%=5%, Value1=Unknown, Value2=50V, ValueDisplayed=10pF
FID1 FID2 FID3 FID4 FID5 FID6: library part CMP-0077181-1, "Fiducial mark.  There is nothing to buy or mount.", Manufacturer=N/A
J1 J2: library part CMP-0055486-1, "TERM BLOCK 2POS 5mm, TH", Manufacturer="Phoenix Contact", Supplier Part Number 1=651-1729018
J3: library part CMP-0075422-1, "Header, 100mil, 10x1, Gold, TH", Color=Black, Current_A=6.3A, Manufacturer=Samtec, Supplier Part Number 1=SAM1029-10-ND, Voltage_V=550V
J4: library part CMP-0054566-1, "Header, 100mil, 2x1, Gold, TH", Color=Black, Current_A=3A, Manufacturer="Sullins Connector Solutions", Supplier Part Number 1=S1011E-02-ND, Voltage_V=1.8kV
J5: library part CMP-0054550-2, "Header, 100mil, 5x2, Tin, TH", Color=Black, Current_A=3A, Manufacturer="Sullins Connector Solutions", Supplier Part Number 1=S2012E-05-ND, Voltage_V=1.8kV
J6: library part CMP-0002334-1, "Header, 100mil, 3x1, Gold, TH", Manufacturer="Sullins Connector Solutions", Supplier Part Number 1=S1011E-03-ND
L1: library part CMP-0092596-1, "Shielded Power Inductors 1.5 µH 10.2A 10.5mOhm Max Nonstandard", Digikey Part Number=2457-XGL4030-152MEC-ND, Manufacturer=Coilcraft, Operating Temperature Range=to, Self Resonant Frequency=50MHz, Test Frequency=1MHz, Tolerance_%=20%
LBL1: library part CMP-0003625-1, Manufacturer=Brady, Supplier Part Number 1=97C5133
Logo1: library part CMP-0074844-1
Logo2: library part CMP-0074838-1, "Texas Instrument Corporate Signature"
Logo3: library part CMP-0074847-1, "FCC_disclaimer"
Logo4: library part CMP-0074769-1
LOGO5: library part CMP-0074837-1, "IEC 61010-1 Hot Surface Warning"
MH1 MH2 MH3 MH4: library part CMP-0078424-2, "PCB Mounting Hole, No Pad", Manufacturer=Any, PartNumber=N/A
R1: library part CMP-0025697-4, "RES, 0, 5%, 0.1 W, AEC-Q200 Grade 0, 0603", Manufacturer=Vishay-Dale, Power_W=100mW, Supplier Part Number 1=541-0.0GCT-ND, TempCo="200 ppm/C", Tolerance_%=5%, Value2=0.1W, Value_Code=0000, ValueDisplayed=0
R2: library part CMP-0081856-1, "RES, 0, 0%, 0.2 W, AEC-Q200 Grade 0, 0402", Manufacturer=Vishay-Dale, Power_W=200mW, Supplier Part Number 1=541-0.0YBTR-ND, Tolerance_%=0%, Value2=0.2W, Value_Code=0
R3: library part CMP-0022095-4, "RES, 187 k, 1%, 0.1 W, AEC-Q200 Grade 0, 0603", Manufacturer=Vishay-Dale, Power_W=100mW, Supplier Part Number 1=541-187KHCT-ND, TempCo="100 ppm/C", Tolerance_%=1%, Value2=0.1W, Value_Code=187k
R4: library part CMP-0022447-4, "RES, 49.9 k, 1%, 0.1 W, AEC-Q200 Grade 0, 0603", Manufacturer=Vishay-Dale, Power_W=100mW, Supplier Part Number 1=541-49.9KHCT-ND, TempCo="100 ppm/C", Tolerance_%=1%, Value2=0.1W, Value_Code=49k9, ValueDisplayed=49.9k
R5: library part CMP-0025963-1, "RES, 10.0, 1%, 0.063 W, 0402", Manufacturer=Vishay-Dale, Power_W=63mW, Supplier Part Number 1=541-10.0LCT-ND, TempCo="100 ppm/C", Tolerance_%=1%, Value2=0.063W, Value_Code=10R0, ValueDisplayed=10.0
R6: library part CMP-0021990-4, "RES, 100 k, 1%, 0.1 W, AEC-Q200 Grade 0, 0603", Manufacturer=Vishay-Dale, PartNumber=CRCW0603100KFKEA, Power_W=100mW, Supplier Part Number 1=541-100KHCT-ND, TempCo="100 ppm/C", Tolerance_%=1%, Value2=0.1W, Value_Code=100k
R7: library part CMP-0025950-3, "RES, 100 k, 1%, 0.063 W, AEC-Q200 Grade 0, 0402", Manufacturer=Vishay-Dale, PartNumber=CRCW0402100KFKED, Power_W=63mW, Supplier Part Number 1=541-100KLCT-ND, TempCo="100 ppm/C", Tolerance_%=1%, Value2=0.063W, Value_Code=100k
R8: library part CMP-0026379-2, "RES, 43.2 k, 1%, 0.063 W, AEC-Q200 Grade 0, 0402", Manufacturer=Vishay-Dale, PartNumber=CRCW040243K2FKED, Power_W=63mW, Supplier Part Number 1=541-43.2KLCT-ND, TempCo="100 ppm/C", Tolerance_%=1%, Value2=0.063W, Value_Code=43k2, ValueDisplayed=43.2k
R9: library part CMP-0026461-2, "RES, 59.0 k, 1%, 0.063 W, AEC-Q200 Grade 0, 0402", Manufacturer=Vishay-Dale, PartNumber=CRCW040259K0FKED, Power_W=63mW, Supplier Part Number 1=541-59.0KLCT-ND, TempCo="100 ppm/C", Tolerance_%=1%, Value2=0.063W, Value_Code=59k0, ValueDisplayed=59.0k
R10: library part CMP-0026367-2, "RES, 40.2 k, 1%, 0.063 W, AEC-Q200 Grade 0, 0402", Manufacturer=Vishay-Dale, Power_W=63mW, Supplier Part Number 1=541-40.2KLCT-ND, TempCo="100 ppm/C", Tolerance_%=1%, Value2=0.063W, Value_Code=40k2, ValueDisplayed=40.2k
R11: library part CMP-0026179-2, "RES, 22.6 k, 1%, 0.063 W, AEC-Q200 Grade 0, 0402", Manufacturer=Vishay-Dale, Power_W=63mW, Supplier Part Number 1=541-22.6KLCT-ND, TempCo="100 ppm/C", Tolerance_%=1%, Value2=0.063W, Value_Code=22k6, ValueDisplayed=22.6k
R12: library part CMP-0026029-3, "RES, 15.8 k, 1%, 0.063 W, AEC-Q200 Grade 0, 0402", Manufacturer=Vishay-Dale, Power_W=63mW, Supplier Part Number 1=541-15.8KLCT-ND, TempCo="100 ppm/C", Tolerance_%=1%, Value2=0.063W, Value_Code=15k8, ValueDisplayed=15.8k
R13: library part CMP-0025975-2, "RES, 11.0 k, 1%, 0.063 W, 0402", Manufacturer=Vishay-Dale, Power_W=63mW, Supplier Part Number 1=541-11.0KLCT-ND, TempCo="100 ppm/C", Tolerance_%=1%, Value2=0.063W, Value_Code=11k0, ValueDisplayed=11.0k
R14: library part CMP-0026966-5, "RES, 6.8 k, 5%, 0.063 W, AEC-Q200 Grade 0, 0402", Manufacturer=Vishay-Dale, Power_W=63mW, Supplier Part Number 1=541-6.8KJCT-ND, TempCo="200 ppm/C", Tolerance_%=5%, Value2=0.063W, Value_Code=6k80, ValueDisplayed=6.8k
R15: library part CMP-0026414-2, "RES, 4.99 k, 1%, 0.063 W, AEC-Q200 Grade 0, 0402", Manufacturer=Vishay-Dale, Power_W=63mW, Supplier Part Number 1=541-4.99KLCT-ND, TempCo="100 ppm/C", Tolerance_%=1%, Value2=0.063W, Value_Code=4k99, ValueDisplayed=4.99k
R16: library part CMP-0022080-4, "RES, 16.5 k, 1%, 0.1 W, AEC-Q200 Grade 0, 0603", Manufacturer=Vishay-Dale, Power_W=100mW, Supplier Part Number 1=541-16.5KHCT-ND, TempCo="100 ppm/C", Tolerance_%=1%, Value2=0.1W, Value_Code=16k5, ValueDisplayed=16.5k
R17: library part CMP-0022468-4, "RES, 4.99 M, 1%, 0.1 W, AEC-Q200 Grade 0, 0603", Manufacturer=Vishay-Dale, Power_W=100mW, Supplier Part Number 1=541-4.99MHCT-ND, TempCo="100 ppm/C", Tolerance_%=1%, Value2=0.1W, Value_Code=4M99, ValueDisplayed=4.99M
SH-J1 SH-J2 SH-J3 SH-J4 SH-J5 SH-J6: library part CMP-0003623-3, "Shunt, 100mil, Gold plated, Black", Alternate Manufacturer=3M, Alternate PartNumber=969102-0000-DA, Manufacturer=Samtec, Supplier Part Number 1=SAM8858-ND
TP1 TP2 TP5 TP6 TP7 TP8: library part CMP-0055162-1, "Test Point, Miniature, SMT", Manufacturer=Keystone, PartNumber=5019, Supplier Part Number 1=36-5019TR-ND
TP3 TP4: library part CMP-0055162-1, "Test Point, Miniature, SMT", Manufacturer=Keystone, Supplier Part Number 1=36-5019TR-ND
U1: library part CMP-0095755-2, Manufacturer="Texas Instruments", Operating Temperature Range=to
ZZ1: library part CMP-0003616-3
ZZ2: library part CMP-0077237-1
ZZ3: library part CMP-0077238-1
ZZ4 ZZ5 ZZ6 ZZ7 ZZ8 ZZ9: library part CMP-0003615-1, "This Assembly Note will show in the PcbDoc and associated outputs"

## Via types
v1: diameter 22, hole 8, Top Layer to Bottom Layer, tented both sides, 213 vias
v2: diameter 20, hole 8, Top Layer to Bottom Layer, tented both sides, 196 vias
v3: diameter 19.68, hole 7.87, Top Layer to Bottom Layer, tented both sides, 8 vias
v4: diameter 22, hole 8, Top Layer to Bottom Layer, 2 vias

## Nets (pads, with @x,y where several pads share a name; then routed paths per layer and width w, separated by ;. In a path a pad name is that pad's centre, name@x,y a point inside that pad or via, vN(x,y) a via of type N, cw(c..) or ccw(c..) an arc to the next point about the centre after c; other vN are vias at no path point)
BODE: C18.1 R5.1 R7.2 TP6.1 | length 765.4
  Top Layer w10: R7.2@1710,1065.91 C18.1@1745.01,1065.91 ; C18.1@1744.06,1067.38 1763.88,1067.38 v1(1771.26,1060) ; R5.1@1745.01,1030.14 C18.1@1745.01,1065.91 ; C18.1@1745.01,1066.43 C18.1@1745.01,1065.91 ; v1(2030,741.81) TP6.1@2030,830
  Signal Layer 2 w10: v1(1771.26,1060) 1851.51,1060 1915.71,995.8 1915.71,733.61 1933.61,715.71 2020.85,715.71 2030,724.86 v1(2030,741.81)
BOOT: C16.2 R2.2 U1.3 | length 133.3
  Top Layer w10: R2.2@1445.09,1122.06 1447.59,1124.56 1463.9,1124.56 1474.41,1135.07 C16.2@1474.41,1163.53 1488.67,1177.8 U1.3@1488.67,1227.8
EN: J3.9 R3.2 R4.2 U1.17 | length 1132.2
  Top Layer w10: v1(1396.49,1628.67) 1396.49,1580 1463.08,1513.41 U1.17@1463.08,1452.2
  Signal Layer 2 w10: J3.9@1140,2236.16 1140,1885.16 v1(1396.49,1628.67)
  Bottom Layer w10: R4.2@1083.33,2106.16 R3.2@1162.95,2106.16 ; J3.9@1141.83,2216.16 1141.83,2169.75 1174.76,2136.82 R3.2@1174.76,2106.16 ; R3.2@1166.89,2106.16 R3.2@1174.76,2098.28
FB: J4.1 R7.1 R8.2 R15.1 U1.8 | length 399.9
  Top Layer w10: U1.8@1616.62,1227.8 1616.62,1192.21 1624.03,1184.8 1628.53,1184.8 1631.03,1182.3 R8.2@1631.03,1177.8 1631.03,1173.3 1669.24,1135.09 1669.24,1108.53 1670.69,1107.07 R15.1@1671.39,1106.38 ; J4.1@1670,855.17 R7.1@1670,1065.91 1670,1106.38 R15.1@1671.39,1107.77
